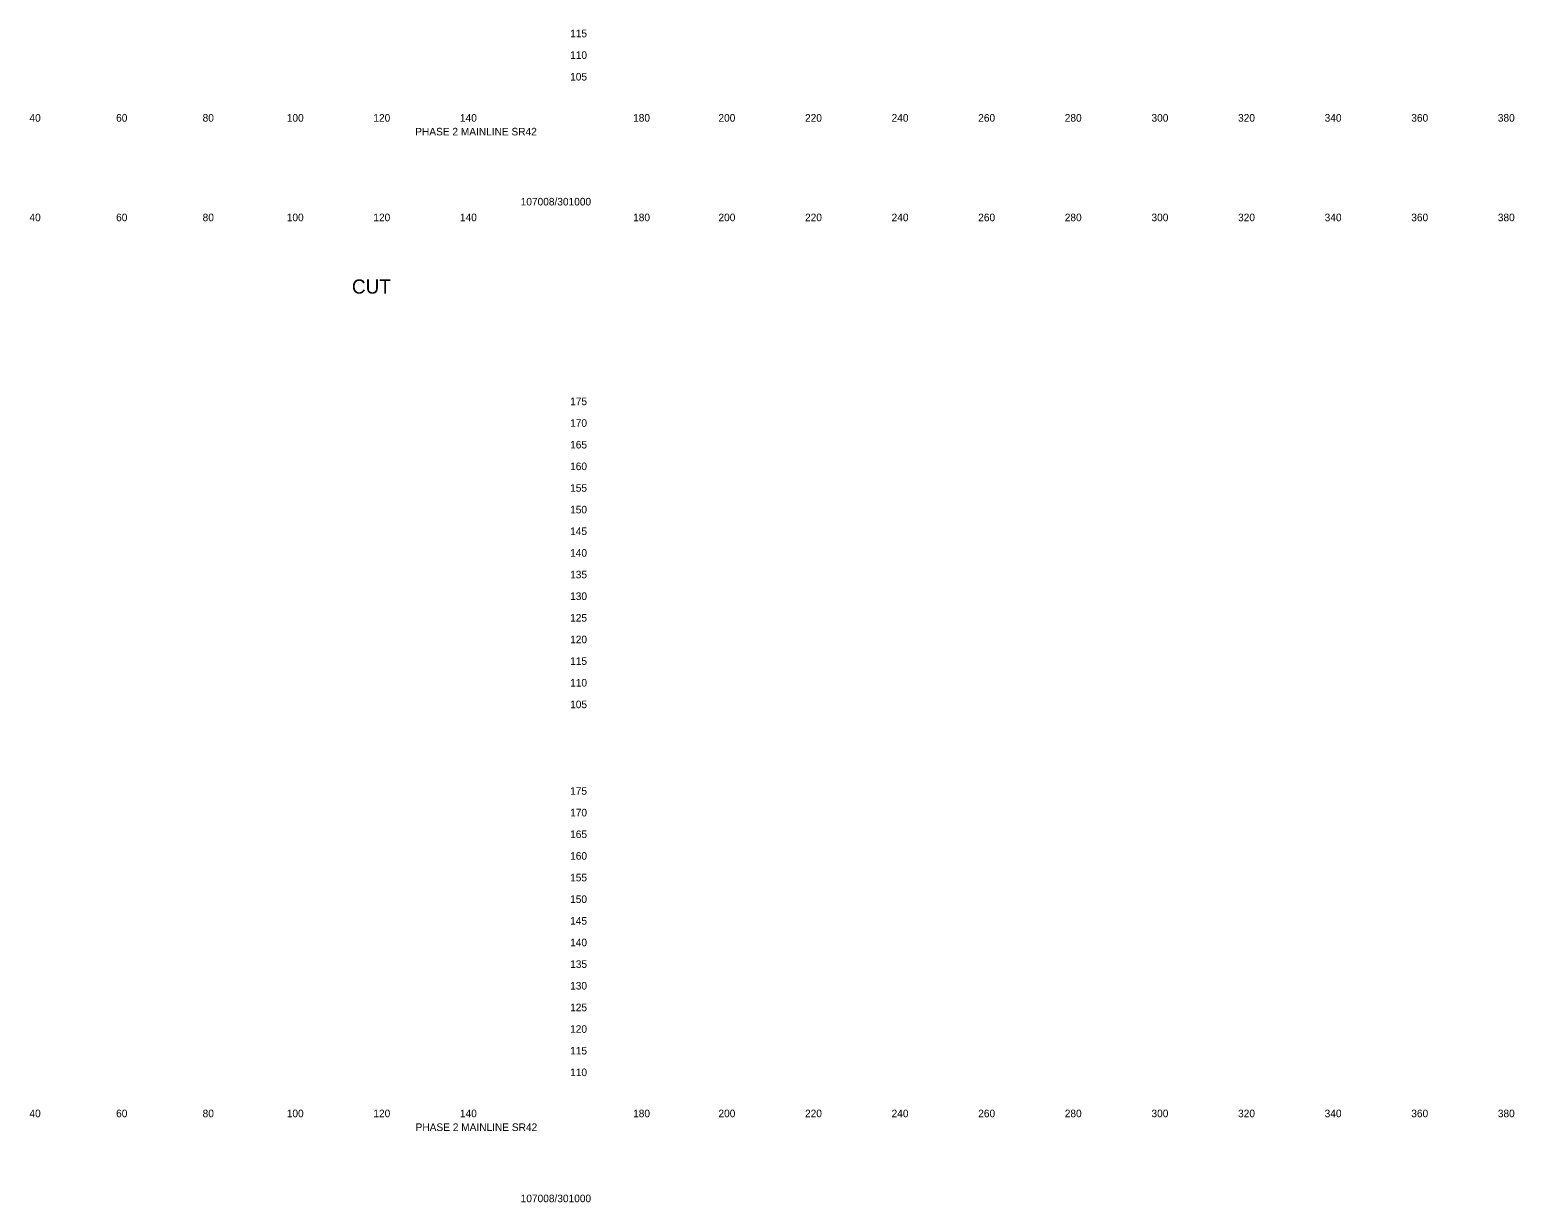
# Model space of a CAD drawing. Extents: x 21281 to 22024, y 6472 to 15208.
# Drawn here: x 21681.3 to 22024.2, y 12205.7 to 12476.6 of the extents above; entities that cross this region are included whole.
import ezdxf

# ---------------------------------------------------------------- set-up
doc = ezdxf.new("R2010")
doc.units = 0
doc.layers.add('XS_SHEET_LABELS_ELEVATION', color=7, linetype='Continuous')
doc.layers.add('XS_SHEET_LABELS_OFFSET', color=7, linetype='Continuous')

msp = doc.modelspace()

# ---------------------------------------------------------------- texts
at = {"layer": 'XS_SHEET_LABELS_ELEVATION'}
for s, p in [('  115  ', (21804.84, 12474.84)), ('  110  ', (21804.84, 12469.84)), ('  105  ', (21804.84, 12464.84)), ('  175  ', (21804.84, 12389.84)), ('  170  ', (21804.84, 12384.84)), ('  165  ', (21804.84, 12379.84)), ('  160  ', (21804.84, 12374.84)), ('  155  ', (21804.84, 12369.84)), ('  150  ', (21804.84, 12364.84)), ('  145  ', (21804.84, 12359.84)), ('  140  ', (21804.84, 12354.84)), ('  135  ', (21804.84, 12349.84)), ('  130  ', (21804.84, 12344.84)), ('  125  ', (21804.84, 12339.84)), ('  120  ', (21804.84, 12334.84)), ('  115  ', (21804.84, 12329.84)), ('  110  ', (21804.84, 12324.84)), ('  105  ', (21804.84, 12319.84)), ('  175  ', (21804.84, 12299.84)), ('  170  ', (21804.84, 12294.84)), ('  165  ', (21804.84, 12289.84)), ('  160  ', (21804.84, 12284.84)), ('  155  ', (21804.84, 12279.84)), ('  150  ', (21804.84, 12274.84)), ('  145  ', (21804.84, 12269.84)), ('  140  ', (21804.84, 12264.84)), ('  135  ', (21804.84, 12259.84)), ('  130  ', (21804.84, 12254.84)), ('  125  ', (21804.84, 12249.84)), ('  120  ', (21804.84, 12244.84)), ('  115  ', (21804.84, 12239.84)), ('  110  ', (21804.84, 12234.84))]:
    msp.add_text(s, height=1.75, dxfattribs=at).set_placement(p)
at = {"layer": 'XS_SHEET_LABELS_OFFSET'}
for s, height, p in [('  40  ', 1.75, (21679.95, 12455.34)), ('  60  ', 1.75, (21699.97, 12455.34)), ('  80  ', 1.75, (21719.95, 12455.34)), ('  100  ', 1.75, (21739.39, 12455.34)), ('  120  ', 1.75, (21759.39, 12455.34)), ('  140  ', 1.75, (21779.39, 12455.34)), ('  180  ', 1.75, (21819.39, 12455.34)), ('  200  ', 1.75, (21839.1, 12455.34)), ('  220  ', 1.75, (21859.1, 12455.34)), ('  240  ', 1.75, (21879.1, 12455.34)), ('  260  ', 1.75, (21899.11, 12455.34)), ('  280  ', 1.75, (21919.1, 12455.34)), ('  300  ', 1.75, (21939.13, 12455.34)), ('  320  ', 1.75, (21959.13, 12455.34)), ('  340  ', 1.75, (21979.13, 12455.34)), ('  360  ', 1.75, (21999.14, 12455.34)), ('  380  ', 1.75, (22019.13, 12455.34)), ('PHASE 2 MAINLINE SR42', 1.75, (21770.36, 12452.16)), ('107008/301000', 1.75, (21794.72, 12435.98)), ('  40  ', 1.75, (21679.95, 12432.34)), ('  60  ', 1.75, (21699.97, 12432.34)), ('  80  ', 1.75, (21719.95, 12432.34)), ('  100  ', 1.75, (21739.39, 12432.34)), ('  120  ', 1.75, (21759.39, 12432.34)), ('  140  ', 1.75, (21779.39, 12432.34)), ('  180  ', 1.75, (21819.39, 12432.34)), ('  200  ', 1.75, (21839.1, 12432.34)), ('  220  ', 1.75, (21859.1, 12432.34)), ('  240  ', 1.75, (21879.1, 12432.34)), ('  260  ', 1.75, (21899.11, 12432.34)), ('  280  ', 1.75, (21919.1, 12432.34)), ('  300  ', 1.75, (21939.13, 12432.34)), ('  320  ', 1.75, (21959.13, 12432.34)), ('  340  ', 1.75, (21979.13, 12432.34)), ('  360  ', 1.75, (21999.14, 12432.34)), ('  380  ', 1.75, (22019.13, 12432.34)), ('CUT', 3.273, (21755.74, 12415.61)), ('  40  ', 1.75, (21679.95, 12225.34)), ('  60  ', 1.75, (21699.97, 12225.34)), ('  80  ', 1.75, (21719.95, 12225.34)), ('  100  ', 1.75, (21739.39, 12225.34)), ('  120  ', 1.75, (21759.39, 12225.34)), ('  140  ', 1.75, (21779.39, 12225.34)), ('  180  ', 1.75, (21819.39, 12225.34)), ('  200  ', 1.75, (21839.1, 12225.34)), ('  220  ', 1.75, (21859.1, 12225.34)), ('  240  ', 1.75, (21879.1, 12225.34)), ('  260  ', 1.75, (21899.11, 12225.34)), ('  280  ', 1.75, (21919.1, 12225.34)), ('  300  ', 1.75, (21939.13, 12225.34)), ('  320  ', 1.75, (21959.13, 12225.34)), ('  340  ', 1.75, (21979.13, 12225.34)), ('  360  ', 1.75, (21999.14, 12225.34)), ('  380  ', 1.75, (22019.13, 12225.34)), ('PHASE 2 MAINLINE SR42', 1.75, (21770.45, 12222.16)), ('107008/301000', 1.75, (21794.72, 12205.71))]:
    msp.add_text(s, height=height, dxfattribs=at).set_placement(p)

doc.saveas('drawing.dxf')
